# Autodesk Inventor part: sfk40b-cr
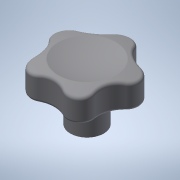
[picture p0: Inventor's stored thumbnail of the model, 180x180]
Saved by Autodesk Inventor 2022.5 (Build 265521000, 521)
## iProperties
Created: 2016-12
Part Number: sfk40b-cr
Material: 一般
Document SubType Name: Modeling
Designer: imaocorp
Density: 1 g/cm^3
Appearance: 既定
Author: imaocorp
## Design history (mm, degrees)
node "sfk40b-cr.x_t1"
node "sfk40b-cr"
node "Base1"
